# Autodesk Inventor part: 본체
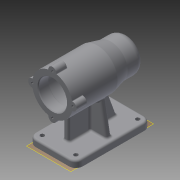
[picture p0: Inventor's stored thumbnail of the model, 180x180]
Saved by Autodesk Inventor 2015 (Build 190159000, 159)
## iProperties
Created: 2019-07
Part Number: 본체
Material: 일반
Document SubType Name: Modeling
Designer: now
Density: 1 g/cm^3
Appearance: 기본값
Author: now
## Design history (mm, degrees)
sketch "스케치1"
  geometry: C1 r 30 at (0, 0); 1 further point
  constraints: 1 centre point, 1 coincident
  dimensions: "d0" = 60 diameter of C1
extrude "돌출1" new body sketch "스케치1" distance "d1" = 16; taper "d2" = 0 deg
sketch "스케치2"
  geometry: C1 r 30 at (0, 0) reference; C2 r 30 at (0, 0)
  constraints: 1 centre point, 1 coincident
  dimensions: "d3" = 60 diameter of C2
extrude "돌출2" join sketch "스케치2" distance "d4" = 51; taper "d5" = 0 deg
sketch "스케치3"
  geometry: L1 (67, 30)-(67, -30) reference; L2 (67, -30)-(0, -30) reference; L3 (0, -30)-(0, 30) reference; L4 (0, 30)-(67, 30) reference; L5 (67, 30)-(67, -30) reference; L6 (67, -30)-(0, -30) reference; L7 (0, -30)-(0, 30) reference; L8 (0, 30)-(67, 30) reference; L9 (87, 25)-(112, 25); L10 (112, 25)-(112, 0); L11 (0, 0)-(112, 0); L12 (0, 30)-(0, -30) reference; L13 (67, 30)-(87, 25); L14 (67, 30)-(67, 0); L15 (67, -30)-(67, 30) reference
  constraints: 10 end point, 2 perpendicular, 1 horizontal, 1 midpoint
  dimensions: "d6" = 25 distance of L9.start L9.end; "d7" = 25 distance between parallel lines of L11 L9; "d8" = 45 distance between parallel lines of L10 L1
revolve "회전1" sketch "스케치3" stored, may be unused: angle "d9" = 90 deg
fillet "모깎기1" dims "d10" = 10
sketch "스케치4"
  geometry: L1 (112, 15)-(112, -15) reference; L2 (102, -25)-(87, -25) reference; L3 (87, -25)-(67, -30) reference; L4 (67, -30)-(0, -30) reference; L5 (0, -30)-(0, 30) reference; L6 (0, 30)-(67, 30) reference; L7 (67, 30)-(87, 25) reference; L8 (87, 25)-(102, 25) reference; L9 (0, 21)-(15, 21); L10 (15, 21)-(15, 0); L11 (15, 21)-(15, 24); L12 (15, 24)-(69, 24); L13 (69, 24)-(69, 0); L14 (69, 21)-(81, 21); L15 (81, 21)-(81, 0); L16 (81, 17.5)-(99, 17.5); L17 (99, 17.5)-(99, 0); L18 (103, 16)-(103, 0); L19 (99, 16)-(103, 16); L20 (106, 10.5)-(106, 0); L21 (0, 0)-(106, 0); L22 (106, 10.5)-(103, 10.5); A1 r 10 centre (102, 15) between (112, 15) and (102, 25) reference; A2 r 10 centre (102, -15) between (102, -25) and (112, -15) reference
  constraints: 28 end point, 7 perpendicular, 5 point on line, 4 vertical, 3 horizontal
  dimensions: "d11" = 15 distance between parallel lines of L10 L5; "d12" = 54 distance between parallel lines of L13 L10; "d13" = 12 distance between parallel lines of L15 L13; "d14" = 18 distance between parallel lines of L17 L15; "d15" = 4 distance between parallel lines of L18 L17; "d16" = 3 distance between parallel lines of L20 L18; "d17" = 21 distance between parallel lines of L21 L9; "d18" = 24 distance between parallel lines of L21 L12; "d19" = 21 distance between parallel lines of L21 L14; "d20" = 17.5 distance between parallel lines of L21 L16; "d22" = 16 distance between parallel lines of L21 L19; "d24" = 10.5 distance between parallel lines of L21 L22
revolve "회전2" sketch "스케치4" stored, may be unused: angle "d25" = 90 deg
node "작업 평면1"
sketch "스케치5"
  geometry: L1 (35, 0)-(-35, 0); L2 (-35, 0)-(-35, 112); L3 (-35, 112)-(35, 112); L4 (35, 112)-(35, 0); L5 (35, 0)-(-35, 112); L6 (-35, 0)-(35, 112); 4 further points
  constraints: 12 end point, 4 midpoint, 2 parallel, 2 vertical alignment, 1 horizontal, 1 perpendicular
  dimensions: "d27" = 112 distance of L1.end L2.end; "d28" = 56 distance of point (0, 56) point (0, 0); "d29" = 70 distance of L2.end L3.end
extrude "돌출3" join sketch "스케치5" distance "d30" = 10; taper "d31" = 0 deg
sketch "스케치6"
  geometry: L1 (-35, 0)-(35, 0) reference; L2 (35, 112)-(-35, 112) reference; L3 (-35, 112)-(-35, 0) reference; L4 (-28, 52)-(28, 52); L5 (28, 52)-(28, 60); L6 (28, 60)-(-28, 60); L7 (-28, 60)-(-28, 52); L8 (-28, 52)-(28, 60); L9 (28, 52)-(-28, 60); L10 (-4, 20)-(4, 20); L11 (4, 20)-(4, 92); L12 (4, 92)-(-4, 92); L13 (-4, 92)-(-4, 20); L14 (-4, 20)-(4, 92); L15 (4, 20)-(-4, 92); 6 further points
  constraints: 24 end point, 7 midpoint, 4 parallel, 2 horizontal, 2 perpendicular, 2 vertical alignment
  dimensions: "d32" = 8 distance between parallel lines of L6 L4; "d33" = 56 distance from line of point (0, 56) L1; "d34" = 7 distance between parallel lines of L3 L7; "d35" = 56 distance of point (0, 0) point (0, 56); "d36" = 20 distance between parallel lines of L2 L12; "d37" = 8 distance between parallel lines of L11 L13
extrude "돌출4" join sketch "스케치6" stored distance "d38" = 10; taper "d39" = 0 deg
feature "면 기울기1" dims angle "d40" = 20 deg
feature "면 기울기2" dims angle "d41" = 10 deg
feature "면 기울기3" dims angle "d42" = 10 deg
fillet "모깎기2" dims "d43" = 10
sketch "스케치7"
  geometry: A1 r 10 centre (-25, 102) between (-25, 112) and (-35, 102) reference; A2 r 10 centre (-25, 10) between (-35, 10) and (-25, 0) reference; A3 r 10 centre (25, 10) between (25, 0) and (35, 10) reference; A4 r 10 centre (25, 102) between (35, 102) and (25, 112) reference; 1 further point
hole "구멍1" sketch "스케치7" at (25, 102), (25, 10), (-25, 102), (-25, 10) diameter "d44" = 6; stored, may be unused: countersink angle "d48" = 90 deg, drill point angle "d50" = 118 deg; dims "d45" = 6, "d46" = 4, "d47" = 2, "d49" = 8
fillet "모깎기3" dims "d51" = 0.3
fillet "모깎기4" dims "d52" = 3
chamfer "모따기1" distance "d53" = 1; stored, may be unused: second distance "d54" = 2, angle "d55" = 45 deg
fillet "모깎기5" dims "d56" = 3
sketch "스케치8"
  geometry: A1 r 30 centre (0, 0) between (0, 30) and (-5.97, 29.4) reference; A2 r 6 centre (0, 30) between (5.97, 29.4) and (-5.97, 29.4)
  constraints: 5 point on circle, 1 centre point, 1 vertical alignment
  dimensions: "d58" = 12 diameter of A2
extrude "돌출5" join sketch "스케치8" distance "d59" = 16; taper "d60" = 0 deg
fillet "모깎기6" dims "d61" = 1
fillet "모깎기7" dims "d62" = 1
sketch "스케치9"
  geometry: A1 r 6 centre (-30, 0) between (-30.171, 5.998) and (-30.171, -5.998) reference; A2 r 6 centre (0, -30) between (-5.998, -30.171) and (5.998, -30.171) reference; A3 r 6 centre (30, 0) between (30.171, -5.998) and (30.171, 5.998) reference; A4 r 6 centre (0, 30) between (5.998, 30.171) and (-5.998, 30.171) reference
hole "구멍2" sketch "스케치9" at (0, 30), (-30, 0), (0, -30), (30, 0) diameter "d66" = 3.242; stored, may be unused: countersink angle "d70" = 90 deg, drill point angle "d72" = 118 deg; dims "d67" = 8, "d68" = 4, "d69" = 2, "d71" = 11
fillet "모깎기9" dims "d75" = 3
fillet "모깎기10" dims "d76" = 3
fillet "모깎기11" dims "d77" = 3
fillet "모깎기12" dims "d78" = 3
node "작업 평면3"
sketch "스케치11"
  geometry: L1 (0, -5.998)-(0, 5.998) reference; 3 further points
  constraints: 1 horizontal alignment, 1 midpoint, 1 other
  dimensions: "d81" = 42 distance from line of L1 point (-42, 0)
feature "엠보싱2" sketch "스케치11" dims "d82" = 0.5, "d83" = 0
node "솔리드1"
pattern_circular "원형 패턴1" dims "d64" = 360 deg
node "절단 모서리 투영1"
node "절단 모서리 투영2"
node "절단 모서리 투영3"
